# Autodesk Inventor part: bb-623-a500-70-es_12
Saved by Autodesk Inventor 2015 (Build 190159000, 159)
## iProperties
Created: 2022-04
Part Number: bb-623-a500-70-es_12
Checked By: TraceParts S.A.
Material: Generic
Catalog Web Link: www.traceparts.com
Document SubType Name: Modeling
Designer: TraceParts
Density: 1 g/cm^3
Appearance: Default
Company: TraceParts S.A.
Author: TraceParts
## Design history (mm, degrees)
feature "bb-623-a500-70-es_12.ipt"
body "Solid1"
